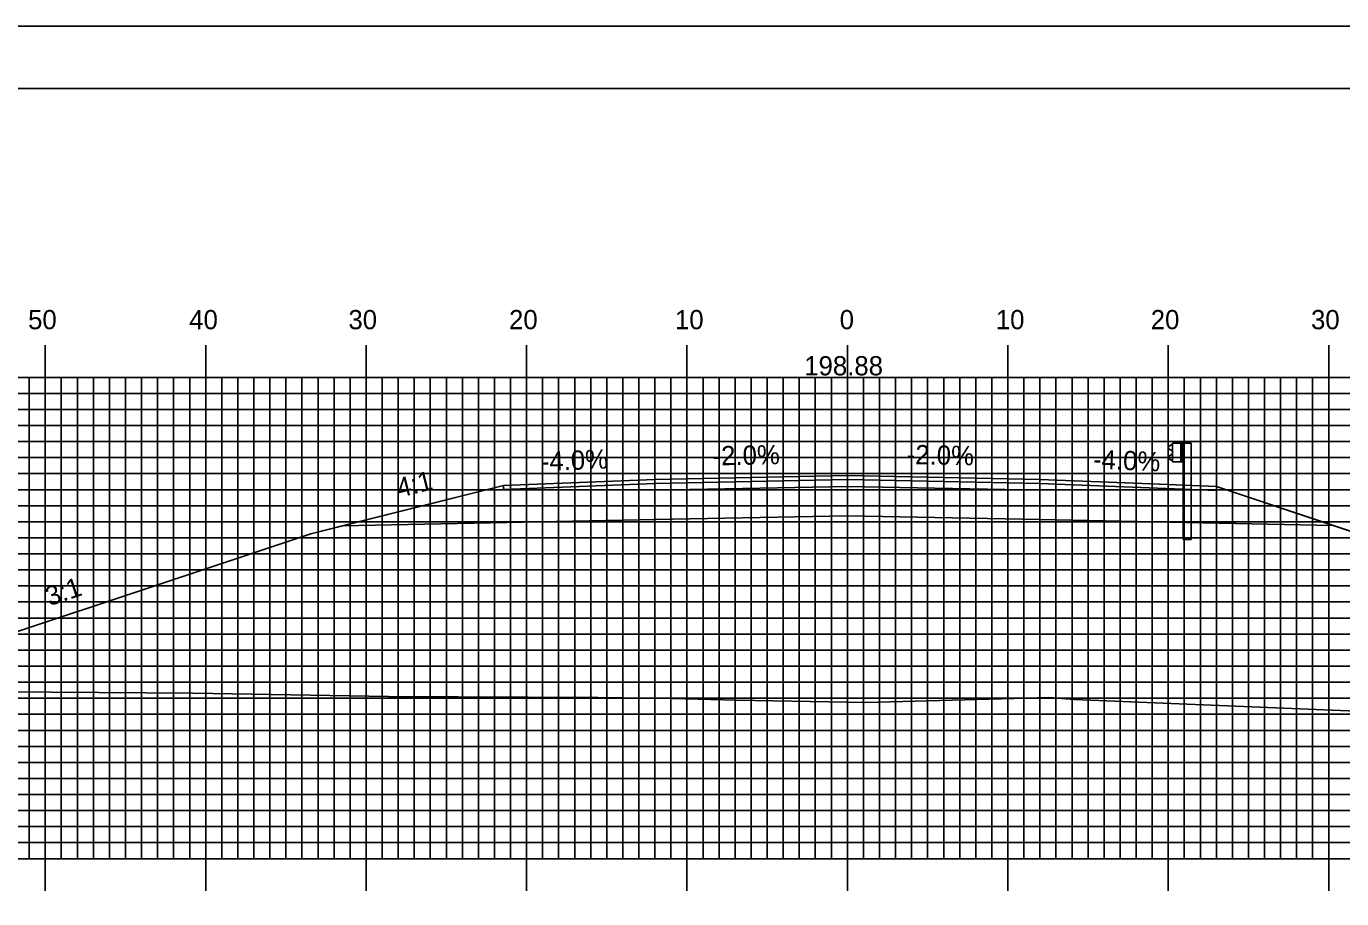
# Model space of a CAD drawing. Extents: x 1808226 to 1808569, y 442591 to 442811.
# Drawn here: x 1808340.1 to 1808422.1, y 442756.2 to 442810.5 of the extents above; entities that cross this region are included whole.
import ezdxf

# ---------------------------------------------------------------- set-up
doc = ezdxf.new("R2010")
doc.units = 0
for name, color, linetype in [('ANNOTATION', 7, 'Continuous'), ('BORDER', 7, 'Continuous'), ('D_Guardrail_Beam_Rt', 7, 'Continuous'), ('D_Roadway_Centerline', 7, 'Continuous'), ('D_Roadway_Centerline_Text', 7, 'Continuous'), ('D_Roadway_Edge_Shoulder', 7, 'Continuous'), ('D_Roadway_Edge_TW', 7, 'Continuous'), ('D_Roadway_Pavement', 7, 'Continuous'), ('D_Roadway_SlopeLines', 7, 'Continuous'), ('D_Roadway_SubGrade', 7, 'Continuous'), ('H_V ANNOTATION', 7, 'Continuous'), ('MAJOR', 7, 'Continuous'), ('MINOR', 7, 'Continuous'), ('PLOT BOUNDARY', 7, 'Continuous'), ('S_Roadway_Centerline', 7, 'Continuous')]:
    doc.layers.add(name, color=color, linetype=linetype)

msp = doc.modelspace()

# ---------------------------------------------------------------- linework, layer by layer
at = {"layer": 'BORDER'}
msp.add_lwpolyline([(1808241.698, 442596.665), (1808561.698, 442596.665), (1808561.698, 442806.665), (1808241.698, 442806.665)], close=True, dxfattribs=at)
at = {"layer": 'D_Guardrail_Beam_Rt'}
for p, q in [((1808411.479, 442784.459), (1808411.335, 442784.359)), ((1808411.569, 442784.481), (1808411.495, 442784.466)), ((1808411.569, 442784.564), (1808412.256, 442784.564)), ((1808411.569, 442783.397), (1808411.569, 442784.564)), ((1808412.09, 442784.564), (1808412.09, 442783.397)), ((1808412.194, 442784.564), (1808412.194, 442783.397)), ((1808412.256, 442784.564), (1808412.727, 442784.564)), ((1808412.256, 442784.564), (1808412.256, 442783.397)), ((1808412.727, 442784.564), (1808412.727, 442778.564)), ((1808411.335, 442784.216), (1808411.531, 442784.08)), ((1808411.531, 442783.881), (1808411.335, 442783.745)), ((1808411.335, 442783.602), (1808411.479, 442783.502)), ((1808411.564, 442784.016), (1808411.564, 442783.946)), ((1808411.495, 442783.495), (1808411.569, 442783.481)), ((1808412.256, 442783.397), (1808411.569, 442783.397)), ((1808412.236, 442778.564), (1808412.236, 442783.397)), ((1808412.236, 442778.564), (1808412.727, 442778.564))]:
    msp.add_line(p, q, dxfattribs=at)
for centre, major_axis, start_param, end_param in [((1808411.503, 442784.425), (-0.0417, 0), 4.907132, 5.323254), ((1808411.386, 442784.288), (-0.0877, 0), 5.323254, 7.243116), ((1808411.386, 442783.673), (-0.0877, 0), 5.323254, 7.243116), ((1808411.486, 442784.016), (0.0789, 0), 0, 0.959931), ((1808411.486, 442783.946), (0.0789, 0), 5.323254, 6.283185), ((1808411.503, 442783.536), (-0.0417, 0), 0.959931, 1.376053)]:
    msp.add_ellipse(centre, major_axis=major_axis, ratio=0.995501, start_param=start_param, end_param=end_param, dxfattribs=at)
at = {"layer": 'D_Roadway_Centerline'}
msp.add_lwpolyline([(1808328.575, 442769.162), (1808357.857, 442778.923), (1808359.808, 442779.411), (1808369.857, 442781.923), (1808379.298, 442782.301), (1808391.298, 442782.541), (1808403.298, 442782.301), (1808411.298, 442781.981), (1808414.298, 442781.861), (1808421.575, 442779.435), (1808456.459, 442767.807)], dxfattribs=at)
at = {"layer": 'D_Roadway_Edge_Shoulder'}
for points in [[(1808379.298, 442782.301), (1808369.857, 442781.923), (1808369.857, 442781.673), (1808379.298, 442782.051)], [(1808403.298, 442782.301), (1808411.298, 442781.981), (1808411.298, 442781.981), (1808414.298, 442781.861), (1808414.298, 442781.611), (1808403.298, 442782.051)]]:
    msp.add_lwpolyline(points, close=True, dxfattribs=at)
at = {"layer": 'D_Roadway_Edge_TW'}
msp.add_lwpolyline([(1808379.298, 442782.051), (1808379.298, 442782.301), (1808391.298, 442782.541), (1808403.298, 442782.301), (1808403.298, 442782.051), (1808391.298, 442782.291)], close=True, dxfattribs=at)
at = {"layer": 'D_Roadway_Pavement'}
msp.add_lwpolyline([(1808379.298, 442781.634), (1808379.298, 442782.051), (1808391.298, 442782.291), (1808403.298, 442782.051), (1808403.298, 442781.634), (1808391.298, 442781.874)], close=True, dxfattribs=at)
at = {"layer": 'D_Roadway_SlopeLines'}
for points in [[(1808369.857, 442781.923), (1808357.857, 442778.923), (1808328.575, 442769.162)], [(1808414.298, 442781.861), (1808456.459, 442767.807)]]:
    msp.add_lwpolyline(points, dxfattribs=at)
at = {"layer": 'D_Roadway_SubGrade'}
for points in [[(1808379.298, 442779.801), (1808359.808, 442779.411), (1808369.857, 442781.923), (1808369.857, 442781.673), (1808379.298, 442782.051)], [(1808379.298, 442779.801), (1808379.298, 442782.051), (1808391.298, 442782.291), (1808403.298, 442782.051), (1808403.298, 442779.801), (1808391.298, 442780.041)], [(1808403.298, 442782.051), (1808414.298, 442781.611), (1808414.298, 442781.861), (1808421.575, 442779.435), (1808403.298, 442779.801)]]:
    msp.add_lwpolyline(points, close=True, dxfattribs=at)
at = {"layer": 'MAJOR'}
for p, q in [((1808341.298, 442790.669), (1808341.298, 442788.665)), ((1808351.298, 442790.669), (1808351.298, 442788.665)), ((1808361.298, 442790.669), (1808361.298, 442788.665)), ((1808371.298, 442790.669), (1808371.298, 442788.665)), ((1808381.298, 442790.669), (1808381.298, 442788.665)), ((1808391.298, 442790.669), (1808391.298, 442788.665)), ((1808401.298, 442790.669), (1808401.298, 442788.665)), ((1808411.298, 442790.669), (1808411.298, 442788.665)), ((1808421.298, 442790.669), (1808421.298, 442788.665)), ((1808251.298, 442788.665), (1808531.298, 442788.665)), ((1808251.298, 442788.665), (1808531.298, 442788.665)), ((1808341.298, 442758.665), (1808341.298, 442788.665)), ((1808351.298, 442758.665), (1808351.298, 442788.665)), ((1808361.298, 442758.665), (1808361.298, 442788.665)), ((1808371.298, 442758.665), (1808371.298, 442788.665)), ((1808381.298, 442758.665), (1808381.298, 442788.665)), ((1808391.298, 442758.665), (1808391.298, 442788.665)), ((1808401.298, 442758.665), (1808401.298, 442788.665)), ((1808411.298, 442758.665), (1808411.298, 442788.665)), ((1808421.298, 442758.665), (1808421.298, 442788.665)), ((1808251.298, 442783.665), (1808531.298, 442783.665)), ((1808251.298, 442778.665), (1808531.298, 442778.665)), ((1808251.298, 442773.665), (1808531.298, 442773.665)), ((1808251.298, 442768.665), (1808531.298, 442768.665)), ((1808251.298, 442763.665), (1808531.298, 442763.665)), ((1808251.298, 442758.665), (1808531.298, 442758.665)), ((1808251.298, 442758.665), (1808531.298, 442758.665)), ((1808341.298, 442756.661), (1808341.298, 442758.665)), ((1808351.298, 442756.661), (1808351.298, 442758.665)), ((1808361.298, 442756.661), (1808361.298, 442758.665)), ((1808371.298, 442756.661), (1808371.298, 442758.665)), ((1808381.298, 442756.661), (1808381.298, 442758.665)), ((1808391.298, 442756.661), (1808391.298, 442758.665)), ((1808401.298, 442756.661), (1808401.298, 442758.665)), ((1808411.298, 442756.661), (1808411.298, 442758.665)), ((1808421.298, 442756.661), (1808421.298, 442758.665))]:
    msp.add_line(p, q, dxfattribs=at)
at = {"layer": 'MINOR'}
for p, q in [((1808340.298, 442758.665), (1808340.298, 442788.665)), ((1808342.298, 442758.665), (1808342.298, 442788.665)), ((1808343.298, 442758.665), (1808343.298, 442788.665)), ((1808344.298, 442758.665), (1808344.298, 442788.665)), ((1808345.298, 442758.665), (1808345.298, 442788.665)), ((1808346.298, 442758.665), (1808346.298, 442788.665)), ((1808347.298, 442758.665), (1808347.298, 442788.665)), ((1808348.298, 442758.665), (1808348.298, 442788.665)), ((1808349.298, 442758.665), (1808349.298, 442788.665)), ((1808350.298, 442758.665), (1808350.298, 442788.665)), ((1808352.298, 442758.665), (1808352.298, 442788.665)), ((1808353.298, 442758.665), (1808353.298, 442788.665)), ((1808354.298, 442758.665), (1808354.298, 442788.665)), ((1808355.298, 442758.665), (1808355.298, 442788.665)), ((1808356.298, 442758.665), (1808356.298, 442788.665)), ((1808357.298, 442758.665), (1808357.298, 442788.665)), ((1808358.298, 442758.665), (1808358.298, 442788.665)), ((1808359.298, 442758.665), (1808359.298, 442788.665)), ((1808360.298, 442758.665), (1808360.298, 442788.665)), ((1808362.298, 442758.665), (1808362.298, 442788.665)), ((1808363.298, 442758.665), (1808363.298, 442788.665)), ((1808364.298, 442758.665), (1808364.298, 442788.665)), ((1808365.298, 442758.665), (1808365.298, 442788.665)), ((1808366.298, 442758.665), (1808366.298, 442788.665)), ((1808367.298, 442758.665), (1808367.298, 442788.665)), ((1808368.298, 442758.665), (1808368.298, 442788.665)), ((1808369.298, 442758.665), (1808369.298, 442788.665)), ((1808370.298, 442758.665), (1808370.298, 442788.665)), ((1808372.298, 442758.665), (1808372.298, 442788.665)), ((1808373.298, 442758.665), (1808373.298, 442788.665)), ((1808374.298, 442758.665), (1808374.298, 442788.665)), ((1808375.298, 442758.665), (1808375.298, 442788.665)), ((1808376.298, 442758.665), (1808376.298, 442788.665)), ((1808377.298, 442758.665), (1808377.298, 442788.665)), ((1808378.298, 442758.665), (1808378.298, 442788.665)), ((1808379.298, 442758.665), (1808379.298, 442788.665)), ((1808380.298, 442758.665), (1808380.298, 442788.665)), ((1808382.298, 442758.665), (1808382.298, 442788.665)), ((1808383.298, 442758.665), (1808383.298, 442788.665)), ((1808384.298, 442758.665), (1808384.298, 442788.665)), ((1808385.298, 442758.665), (1808385.298, 442788.665)), ((1808386.298, 442758.665), (1808386.298, 442788.665)), ((1808387.298, 442758.665), (1808387.298, 442788.665)), ((1808388.298, 442758.665), (1808388.298, 442788.665)), ((1808389.298, 442758.665), (1808389.298, 442788.665)), ((1808390.298, 442758.665), (1808390.298, 442788.665)), ((1808392.298, 442758.665), (1808392.298, 442788.665)), ((1808393.298, 442758.665), (1808393.298, 442788.665)), ((1808394.298, 442758.665), (1808394.298, 442788.665)), ((1808395.298, 442758.665), (1808395.298, 442788.665)), ((1808396.298, 442758.665), (1808396.298, 442788.665)), ((1808397.298, 442758.665), (1808397.298, 442788.665)), ((1808398.298, 442758.665), (1808398.298, 442788.665)), ((1808399.298, 442758.665), (1808399.298, 442788.665)), ((1808400.298, 442758.665), (1808400.298, 442788.665)), ((1808402.298, 442758.665), (1808402.298, 442788.665)), ((1808403.298, 442758.665), (1808403.298, 442788.665)), ((1808404.298, 442758.665), (1808404.298, 442788.665)), ((1808405.298, 442758.665), (1808405.298, 442788.665)), ((1808406.298, 442758.665), (1808406.298, 442788.665)), ((1808407.298, 442758.665), (1808407.298, 442788.665)), ((1808408.298, 442758.665), (1808408.298, 442788.665)), ((1808409.298, 442758.665), (1808409.298, 442788.665)), ((1808410.298, 442758.665), (1808410.298, 442788.665)), ((1808412.298, 442758.665), (1808412.298, 442788.665)), ((1808413.298, 442758.665), (1808413.298, 442788.665)), ((1808414.298, 442758.665), (1808414.298, 442788.665)), ((1808415.298, 442758.665), (1808415.298, 442788.665)), ((1808416.298, 442758.665), (1808416.298, 442788.665)), ((1808417.298, 442758.665), (1808417.298, 442788.665)), ((1808418.298, 442758.665), (1808418.298, 442788.665)), ((1808419.298, 442758.665), (1808419.298, 442788.665)), ((1808420.298, 442758.665), (1808420.298, 442788.665)), ((1808251.298, 442787.665), (1808531.298, 442787.665)), ((1808251.298, 442786.665), (1808531.298, 442786.665)), ((1808251.298, 442785.665), (1808531.298, 442785.665)), ((1808251.298, 442784.665), (1808531.298, 442784.665)), ((1808251.298, 442782.665), (1808531.298, 442782.665)), ((1808251.298, 442781.665), (1808531.298, 442781.665)), ((1808251.298, 442780.665), (1808531.298, 442780.665)), ((1808251.298, 442779.665), (1808531.298, 442779.665)), ((1808251.298, 442777.665), (1808531.298, 442777.665)), ((1808251.298, 442776.665), (1808531.298, 442776.665)), ((1808251.298, 442775.665), (1808531.298, 442775.665)), ((1808251.298, 442774.665), (1808531.298, 442774.665)), ((1808251.298, 442772.665), (1808531.298, 442772.665)), ((1808251.298, 442771.665), (1808531.298, 442771.665)), ((1808251.298, 442770.665), (1808531.298, 442770.665)), ((1808251.298, 442769.665), (1808531.298, 442769.665)), ((1808251.298, 442767.665), (1808531.298, 442767.665)), ((1808251.298, 442766.665), (1808531.298, 442766.665)), ((1808251.298, 442765.665), (1808531.298, 442765.665)), ((1808251.298, 442764.665), (1808531.298, 442764.665)), ((1808251.298, 442762.665), (1808531.298, 442762.665)), ((1808251.298, 442761.665), (1808531.298, 442761.665)), ((1808251.298, 442760.665), (1808531.298, 442760.665)), ((1808251.298, 442759.665), (1808531.298, 442759.665))]:
    msp.add_line(p, q, dxfattribs=at)
at = {"layer": 'PLOT BOUNDARY'}
msp.add_lwpolyline([(1808225.511, 442590.547), (1808565.511, 442590.547), (1808565.511, 442810.547), (1808225.511, 442810.547)], close=True, dxfattribs=at)
at = {"layer": 'S_Roadway_Centerline'}
msp.add_lwpolyline([(1808324.684, 442769.199), (1808341.693, 442769.04), (1808350.51, 442768.98), (1808362.688, 442768.774), (1808375.736, 442768.721), (1808380.405, 442768.654), (1808384.368, 442768.546), (1808392.456, 442768.406), (1808401.679, 442768.654), (1808403.844, 442768.71), (1808405.457, 442768.589), (1808426.542, 442767.722), (1808428.009, 442767.724), (1808438.501, 442767.732), (1808448.655, 442767.8), (1808453.858, 442767.798), (1808462.196, 442767.827), (1808469.651, 442767.515), (1808484.823, 442767.779), (1808489.798, 442767.633), (1808504.339, 442767.393), (1808512.596, 442767.294), (1808530.865, 442766.487), (1808531.298, 442766.484)], dxfattribs=at)

# ---------------------------------------------------------------- texts
at = {"layer": 'ANNOTATION'}
for s, rotation, p in [('-2.0%', 1.14576, (1808382.904, 442783.173)), ('-2.0%', 358.85424, (1808394.984, 442783.267)), ('-4.0%', 2.29061, (1808372.209, 442782.819)), ('-4.0%', 357.70939, (1808406.59, 442782.971)), ('4:1', 14.03624, (1808363.368, 442781.162)), ('3:1', 18.43478, (1808341.555, 442774.397))]:
    msp.add_text(s, height=1.2, rotation=rotation, dxfattribs=at).set_placement(p)
at = {"layer": 'D_Roadway_Centerline'}
for s, p in [('C', (1808391.293, 442782.541)), ('L', (1808391.298, 442782.533))]:
    msp.add_text(s, height=0.0146, dxfattribs=at).set_placement(p)
at = {"layer": 'D_Roadway_Centerline_Text'}
msp.add_text('198.88', height=1.2, dxfattribs=at).set_placement((1808388.607, 442788.789))
at = {"layer": 'H_V ANNOTATION'}
for s, p in [('50', (1808340.227, 442791.665)), ('40', (1808350.27, 442791.665)), ('30', (1808360.195, 442791.665)), ('20', (1808370.206, 442791.665)), ('10', (1808380.549, 442791.665)), ('0', (1808390.816, 442791.665)), ('10', (1808400.549, 442791.665)), ('20', (1808410.206, 442791.665)), ('30', (1808420.195, 442791.665))]:
    msp.add_text(s, height=1.2, dxfattribs=at).set_placement(p)

doc.saveas('drawing.dxf')
